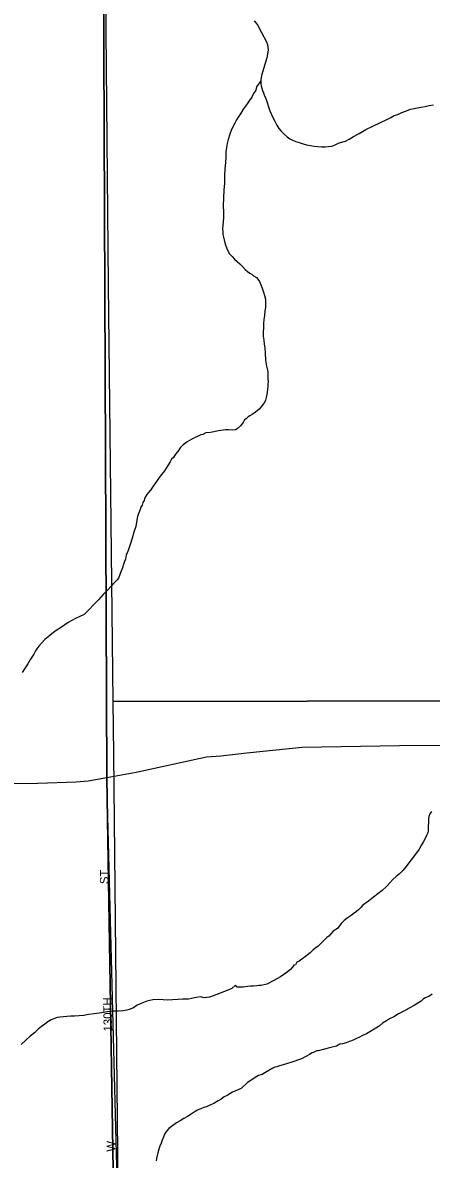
# Model space of a CAD drawing. Extents: x 2010165 to 2382125, y 1060529 to 1407316.
# Drawn here: x 2164475 to 2166876, y 1197412 to 1204103 of the extents above; entities that cross this region are included whole.
import ezdxf

# ---------------------------------------------------------------- set-up
doc = ezdxf.new("R2010")
doc.units = 0
for name, color, linetype in [('GM_X_City_Street', 7, 'Continuous'), ('GM_X_City_Street_Text', 7, 'Continuous'), ('GM_X_Corporation', 7, 'Continuous'), ('GM_X_Major_River', 7, 'Continuous'), ('GM_X_Minor_River', 7, 'Continuous'), ('GM_X_Section', 7, 'Continuous')]:
    doc.layers.add(name, color=color, linetype=linetype)

msp = doc.modelspace()

# ---------------------------------------------------------------- linework, layer by layer
at = {"layer": 'GM_X_City_Street'}
for points in [[(2165067.2, 1195844.8), (2164968.9, 1199659.4), (2164935.2, 1207756.2), (2164931.8, 1207897.8), (2164931.2, 1207965.8)], [(2164968.9, 1199659.4), (2165140.7, 1199691.1), (2165553.9, 1199781.2), (2165639.8, 1199788), (2165791.7, 1199805.5), (2166117.4, 1199838.6), (2166689.3, 1199848), (2169131.1, 1199856.7), (2169949, 1199862.3)], [(2159147.8, 1199516.5), (2163951.3, 1199619.8), (2164563.3, 1199625.6), (2164789.3, 1199635), (2164858.5, 1199640.9), (2164968.9, 1199659.4)]]:
    msp.add_lwpolyline(points, dxfattribs=at)
at = {"layer": 'GM_X_Corporation'}
for points in [[(2186878.7, 1221701), (2186923.4, 1220744.1), (2186933.5, 1220238.7), (2186941.3, 1219753.4), (2186978.3, 1216841.2), (2187013.9, 1213879), (2187027.1, 1208132.6), (2187205, 1194725.9), (2177123.5, 1194567.9), (2176176.5, 1194580.3), (2174206.9, 1194531), (2167776.4, 1194381.4), (2165054.7, 1194304.8), (2164968.9, 1199659.4), (2164935.2, 1207756.2), (2164931.8, 1207897.8), (2164930.1, 1208081.5), (2164898.5, 1211429), (2164844.7, 1216037.6), (2164832.8, 1218637), (2164895.8, 1221436.7)], [(2164895.8, 1221436.7), (2164832.8, 1218637), (2164844.7, 1216037.6), (2164898.5, 1211429), (2164930.1, 1208081.5), (2164931.8, 1207897.8), (2164935.2, 1207756.2), (2164968.9, 1199659.4), (2165054.7, 1194304.8), (2162687.3, 1194296.8), (2162163.4, 1194282.6), (2161645.6, 1194276.5), (2161453.7, 1194270.4), (2159224.5, 1194187.1), (2158831.1, 1194172.4), (2158006.9, 1194141.9), (2154020.1, 1193994.5), (2151351.3, 1193919.5)]]:
    msp.add_lwpolyline(points, dxfattribs=at)
at = {"layer": 'GM_X_Major_River'}
msp.add_lwpolyline([(2165835.6, 1204114.1), (2165847.8, 1204100.2), (2165858, 1204084.3), (2165868.3, 1204064.3), (2165878.5, 1204046.4), (2165907.3, 1203990.6), (2165913.5, 1203974.6), (2165918, 1203942.6), (2165908.6, 1203896.3), (2165895.1, 1203852), (2165885.6, 1203817.8), (2165877.9, 1203793.6), (2165876, 1203779.6), (2165874.2, 1203769.5), (2165874.4, 1203753.4), (2165874.5, 1203743.4), (2165876.7, 1203731.4), (2165880.9, 1203717.4), (2165885, 1203703.4), (2165889.2, 1203691.4), (2165893.4, 1203679.4), (2165899.6, 1203665.5), (2165905.8, 1203651.5), (2165912, 1203633.5), (2165918.3, 1203613.6), (2165926.7, 1203585.6), (2165937, 1203563.6), (2165947.3, 1203541.7), (2165957.6, 1203519.7), (2165967.9, 1203499.8), (2165980.1, 1203479.9), (2165994.4, 1203464), (2166010.6, 1203448.2), (2166028.8, 1203432.3), (2166045, 1203420.5), (2166061.2, 1203412.7), (2166079.3, 1203404.9), (2166105.4, 1203397.2), (2166123.6, 1203389.4), (2166143.7, 1203383.6), (2166165.8, 1203379.8), (2166187.9, 1203376.1), (2166209.9, 1203374.4), (2166232, 1203372.6), (2166252, 1203372.9), (2166272, 1203375.1), (2166292, 1203377.4), (2166312, 1203383.6), (2166335.8, 1203396), (2166371.8, 1203406.4), (2166393.7, 1203418.8), (2166419.5, 1203433.1), (2166453.3, 1203451.6), (2166491.1, 1203474.1), (2166614.5, 1203533.8), (2166638.4, 1203546.1), (2166658.3, 1203556.4), (2166680.3, 1203562.7), (2166704.1, 1203575), (2166730.1, 1203585.4), (2166754, 1203593.7), (2166776, 1203598), (2166796, 1203602.2), (2166815.9, 1203606.5), (2166839.9, 1203610.8), (2166863.9, 1203615.1), (2166889.9, 1203619.4)], dxfattribs=at)
at = {"layer": 'GM_X_Minor_River'}
for points in [[(2165874.3, 1203761.8), (2165848.7, 1203725), (2165844.9, 1203706.9), (2165831.2, 1203686.7), (2165821.4, 1203664.5), (2165805.7, 1203644.3), (2165793.9, 1203626.1), (2165782.1, 1203609.9), (2165768.3, 1203589.6), (2165754.6, 1203567.4), (2165740.8, 1203547.2), (2165731, 1203531), (2165721.3, 1203512.8), (2165709.5, 1203490.6), (2165699.8, 1203468.4), (2165692.1, 1203446.3), (2165682.5, 1203416.1), (2165676.8, 1203391.9), (2165673.1, 1203367.8), (2165669.4, 1203343.7), (2165667.8, 1203313.6), (2165666.2, 1203281.4), (2165662.7, 1203243.3), (2165661.2, 1203201.1), (2165659.8, 1203159), (2165656.3, 1203116.8), (2165654.9, 1203072.6), (2165653.5, 1203024.5), (2165654, 1202988.4), (2165654.5, 1202954.3), (2165649.3, 1202890), (2165651.5, 1202874), (2165651.7, 1202855.9), (2165653.9, 1202839.9), (2165658.1, 1202825.9), (2165662.4, 1202807.9), (2165668.6, 1202789.9), (2165679, 1202764), (2165689.3, 1202742), (2165705.5, 1202726.2), (2165719.7, 1202712.3), (2165735.9, 1202698.5), (2165750.1, 1202684.6), (2165766.4, 1202668.8), (2165782.6, 1202650.9), (2165796.8, 1202639), (2165809, 1202629.1), (2165821.1, 1202623.3), (2165831.2, 1202613.4), (2165849.4, 1202603.6), (2165857.5, 1202593.6), (2165865.7, 1202579.7), (2165874, 1202559.7), (2165882.3, 1202539.8), (2165890.6, 1202517.8), (2165896.8, 1202497.8), (2165901.1, 1202475.8), (2165901.5, 1202449.7), (2165901.8, 1202427.6), (2165898, 1202407.5), (2165896.4, 1202379.4), (2165892.7, 1202355.3), (2165889, 1202333.2), (2165889.3, 1202307.1), (2165887.7, 1202281), (2165887.9, 1202258.9), (2165892.3, 1202234.9), (2165894.6, 1202210.9), (2165896.9, 1202188.8), (2165899.3, 1202158.8), (2165901.8, 1202116.7), (2165908.3, 1202080.6), (2165912.6, 1202058.6), (2165914.8, 1202046.6), (2165914.9, 1202034.6), (2165915.1, 1202020.5), (2165915.3, 1202006.5), (2165917.5, 1201988.5), (2165915.7, 1201974.4), (2165915.9, 1201960.4), (2165910.5, 1201914.1), (2165904.7, 1201896), (2165900.9, 1201881.9), (2165895.1, 1201867.8), (2165885.2, 1201855.6), (2165875.4, 1201841.5), (2165863.6, 1201827.3), (2165843.7, 1201811), (2165823.9, 1201796.7), (2165810, 1201788.5), (2165800, 1201782.4), (2165788.1, 1201772.2), (2165778.2, 1201766.1), (2165770.4, 1201749.9), (2165754.6, 1201729.7), (2165734.8, 1201713.4), (2165724.9, 1201707.2), (2165706.9, 1201705), (2165684.8, 1201706.7), (2165666.8, 1201706.5), (2165624.8, 1201700)], [(2165624.8, 1201700), (2165578.8, 1201691.4), (2165550.8, 1201689), (2165532.9, 1201678.8), (2165520.9, 1201676.6), (2165469.2, 1201651.9), (2165441.3, 1201635.5), (2165417.5, 1201619.2), (2165399.7, 1201600.9), (2165386, 1201578.7), (2165372.2, 1201562.4), (2165360.4, 1201544.3), (2165348.5, 1201534.1), (2165340.7, 1201517.9), (2165326.9, 1201495.7), (2165307.3, 1201465.4), (2165281.7, 1201432.9), (2165260, 1201402.6), (2165240.4, 1201374.2), (2165224.7, 1201352), (2165214.8, 1201337.8), (2165205, 1201325.7), (2165199.1, 1201315.6), (2165191.3, 1201301.4), (2165187.4, 1201291.3), (2165181.5, 1201279.2), (2165175.7, 1201263.1), (2165167.9, 1201251), (2165164.1, 1201236.9), (2165160.2, 1201226.8), (2165152.4, 1201208.6), (2165148.6, 1201196.6), (2165144.8, 1201174.5), (2165139.3, 1201138.3), (2165127.7, 1201104), (2165118.2, 1201067.8), (2165106.6, 1201031.5), (2165095.1, 1200995.3), (2165083.4, 1200969.1), (2165077.7, 1200944.9), (2165071.9, 1200930.8), (2165066.1, 1200914.7), (2165060.3, 1200894.5), (2165052.6, 1200874.4), (2165044.8, 1200854.2), (2165037.1, 1200834.1), (2165029.2, 1200823.9), (2165017.4, 1200811.7), (2165007.5, 1200801.6), (2164993.7, 1200785.4), (2164973.9, 1200765.1), (2164948.2, 1200736.7), (2164920.6, 1200706.2), (2164835.6, 1200618.9), (2164783.8, 1200596.2), (2164742, 1200571.6), (2164702.3, 1200545.1), (2164664.6, 1200520.5), (2164632.8, 1200496), (2164605.1, 1200471.6), (2164585.3, 1200451.3), (2164569.5, 1200433.1), (2164557.7, 1200416.9), (2164549.9, 1200404.7), (2164540.1, 1200386.6), (2164520.4, 1200356.2), (2164504.8, 1200329.9), (2164489, 1200305.7), (2164471.4, 1200277.4)], [(2166878.2, 1199460.2), (2166868.4, 1199446), (2166862.6, 1199429.9)], [(2166862.6, 1199429.9), (2166860.8, 1199415.8), (2166859.1, 1199393.7), (2166857.3, 1199375.7), (2166857.5, 1199357.6), (2166857.7, 1199345.6), (2166855.8, 1199333.5), (2166848, 1199317.4), (2166840.2, 1199301.2), (2166830.5, 1199283), (2166818.7, 1199262.8), (2166805, 1199238.6), (2166789.3, 1199216.3), (2166726.2, 1199133.3), (2166708.5, 1199113), (2166688.7, 1199092.7), (2166670.9, 1199076.4), (2166651.1, 1199060.1), (2166633.3, 1199039.8), (2166613.6, 1199017.5), (2166587.8, 1198995.1), (2166562, 1198974.8), (2166536.2, 1198954.4), (2166506.5, 1198932), (2166488.6, 1198917.7), (2166474.7, 1198907.5), (2166462.9, 1198895.3), (2166449, 1198881.1), (2166437.2, 1198870.9), (2166423.3, 1198860.7), (2166405.4, 1198846.4), (2166381.6, 1198832.1), (2166363.7, 1198817.8), (2166345.9, 1198799.6), (2166324.3, 1198771.2), (2166300.4, 1198754.9), (2166286.6, 1198738.6), (2166274.8, 1198726.5), (2166262.8, 1198718.3), (2166253, 1198708.1), (2166241.1, 1198696), (2166227.3, 1198681.7), (2166211.4, 1198667.5), (2166197.5, 1198657.3), (2166181.7, 1198645.1), (2166163.9, 1198626.8), (2166136.1, 1198606.4), (2166116.3, 1198590.1), (2166100.4, 1198577.9), (2166086.5, 1198571.7), (2166078.6, 1198557.5), (2166068.6, 1198555.4), (2166060.8, 1198543.3), (2166048.9, 1198529.1), (2166021.2, 1198508.7), (2165989.4, 1198486.2), (2165951.6, 1198463.7), (2165909.8, 1198443.1), (2165875.9, 1198434.7), (2165861.9, 1198434.5), (2165849.9, 1198432.3), (2165831.8, 1198432.1), (2165813.8, 1198431.9), (2165795.8, 1198429.7), (2165769.8, 1198425.3), (2165747.8, 1198425.1), (2165735.8, 1198424.9), (2165725.6, 1198436.8), (2165703.8, 1198418.5), (2165632.1, 1198387.5), (2165572.2, 1198366.7), (2165540.2, 1198362.3), (2165520.1, 1198368.1), (2165494.2, 1198363.8), (2165466.2, 1198359.4), (2165448.2, 1198355.2), (2165434.2, 1198355), (2165416.1, 1198354.8), (2165388.1, 1198352.4), (2165354.1, 1198350), (2165326, 1198349.7), (2165300, 1198351.4), (2165269.9, 1198353), (2165239.9, 1198350.6), (2165203.9, 1198342.2), (2165174, 1198331.8), (2165148.1, 1198319.4), (2165126.3, 1198303.1), (2165100.4, 1198294.7), (2165086.4, 1198290.6), (2165064.4, 1198286.3), (2165038.4, 1198283.9), (2165006.4, 1198283.6), (2164972.3, 1198281.1), (2164938.4, 1198274.7), (2164894.4, 1198268.1), (2164860.4, 1198263.7), (2164834.4, 1198259.4), (2164806.4, 1198257), (2164778.3, 1198254.7), (2164754.3, 1198254.4)], [(2166882.3, 1198384.8), (2166862.4, 1198370.5), (2166840.5, 1198362.2), (2166828.6, 1198354), (2166816.7, 1198343.9), (2166796.8, 1198331.6), (2166775, 1198317.3), (2166747.1, 1198300.9), (2166715.3, 1198284.4), (2166683.5, 1198268), (2166655.6, 1198251.6), (2166631.7, 1198239.3), (2166613.9, 1198227), (2166590, 1198212.7)], [(2164754.3, 1198254.4), (2164692.3, 1198249.6), (2164676.3, 1198247.4), (2164660.3, 1198241.2), (2164642.4, 1198232.9), (2164622.5, 1198220.7), (2164604.6, 1198208.4), (2164584.8, 1198194.1), (2164565, 1198177.8), (2164543.2, 1198157.5), (2164517.4, 1198137.1), (2164491.7, 1198112.7), (2164466, 1198088.3)], [(2166590, 1198212.7), (2166570.2, 1198196.4), (2166494.6, 1198151.3), (2166472.8, 1198141), (2166454.8, 1198130.8), (2166436.9, 1198122.5), (2166417, 1198114.2), (2166395.1, 1198105.9), (2166375.1, 1198097.7), (2166355.2, 1198091.4), (2166339.2, 1198089.2), (2166329.3, 1198083.1), (2166319.3, 1198078.9), (2166285.3, 1198070.5), (2166241.4, 1198057.9), (2166211.5, 1198051.5), (2166201.5, 1198051.4), (2166187.5, 1198043.2), (2166175.6, 1198039.1), (2166159.7, 1198028.8), (2166139.8, 1198016.6), (2166113.9, 1198004.2), (2166090, 1197995.9), (2166074, 1197989.7), (2166056.1, 1197983.4), (2166030.1, 1197975.1), (2166006.2, 1197968.8), (2165984.2, 1197962.5), (2165968.3, 1197956.3), (2165956.3, 1197954.1), (2165944.4, 1197947.9), (2165898.6, 1197921.3), (2165882.7, 1197911.1), (2165860.8, 1197904.8), (2165840.9, 1197894.5), (2165821, 1197880.2), (2165795.2, 1197863.8), (2165759.6, 1197829.3), (2165707.8, 1197806.6), (2165676, 1197788.1), (2165658.1, 1197779.9), (2165640.2, 1197765.6), (2165624.3, 1197755.4), (2165598.5, 1197741), (2165578.5, 1197732.8), (2165558.6, 1197722.5), (2165538.7, 1197716.2), (2165520.7, 1197710), (2165508.8, 1197705.8), (2165498.8, 1197699.7), (2165482.9, 1197689.5), (2165465.1, 1197677.2), (2165443.2, 1197664.9), (2165421.3, 1197652.6), (2165399.5, 1197638.3), (2165377.6, 1197626), (2165363.7, 1197615.8), (2165349.8, 1197605.6), (2165333.9, 1197593.3), (2165320.1, 1197577.1), (2165308.3, 1197560.9), (2165302.5, 1197542.8), (2165294.8, 1197524.6), (2165289, 1197506.5), (2165281.2, 1197488.4), (2165275.4, 1197472.2), (2165269.7, 1197450.1), (2165263.9, 1197434), (2165260.1, 1197415.9), (2165258.3, 1197403.8)]]:
    msp.add_lwpolyline(points, dxfattribs=at)
at = {"layer": 'GM_X_Section'}
for points in [[(2164951, 1205618.4), (2170618.6, 1205608.5), (2170707.4, 1200117.9), (2165006.1, 1200107.3), (2164978.9, 1202559.4), (2164951.3, 1205550)], [(2170707.4, 1200117.9), (2170798.5, 1194480.2), (2168279.1, 1194421.6), (2165085.3, 1194362.3), (2165037.5, 1197060.2), (2165009.9, 1199797.8), (2165006.1, 1200107.3)]]:
    msp.add_lwpolyline(points, close=True, dxfattribs=at)

# ---------------------------------------------------------------- texts
at = {"layer": 'GM_X_City_Street_Text'}
for s, rotation, p in [('ST', 90, (2164978.4, 1199032)), ('130TH', 91.16842, (2165000.5, 1198165.1)), ('W', 90, (2165018.1, 1197456.8))]:
    msp.add_text(s, height=50, rotation=rotation, dxfattribs=at).set_placement(p)

doc.saveas('drawing.dxf')
